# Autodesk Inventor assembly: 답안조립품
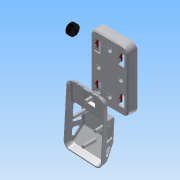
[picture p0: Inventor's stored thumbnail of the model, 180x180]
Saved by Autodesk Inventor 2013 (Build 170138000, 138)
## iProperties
Created: 2015-05
Part Number: 답안조립품
Document SubType Name: Assembly
Designer: Administrator
Author: Administrator
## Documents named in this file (7)
- C:\Documents and Settings\Administrator\바탕 화면\450507V1017\답안조립품.iam
- C:\Documents and Settings\Administrator\바탕 화면\450507V1017\1-본체.ipt
- C:\Documents and Settings\Administrator\바탕 화면\450507V1017\커버.ipt
- C:\Documents and Settings\Administrator\바탕 화면\450507V1017\바퀴.ipt
- C:\Documents and Settings\Administrator\바탕 화면\450507V1017\바퀴고정부.ipt
- C:\Documents and Settings\Administrator\바탕 화면\450507V1017\바퀴고정부_MIR.ipt
- C:\Documents and Settings\Administrator\바탕 화면\450507V1017\M2x4.ipt
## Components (17 placed, 2 different names)
1. M2x4:1
2. M2x4:2
3. M2x4:3
4. M2x4:4
5. M2x4:5
6. M2x4:6
7. M2x4:7
8. M2x4:8
9. M2x4:9
10. M2x4:10
11. M2x4:11
12. M2x4:12
13. M2x4:13
14. M2x4:14
15. M2x4:15
16. M2x4:16
17. 1-본체:1
